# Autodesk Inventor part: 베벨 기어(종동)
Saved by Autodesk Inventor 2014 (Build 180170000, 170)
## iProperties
Created: 2026-05
Part Number: 베벨 기어(종동)
Material: 일반
Document SubType Name: Modeling
Designer: dg
Density: 1 g/cm^3
Appearance: 기본값
Author: dg
Author: jhkim
Creation Date: 2026-04-23
Sending System: Autodesk Inventor 2027
Preprocessor: ST-DEVELOPER v20.1
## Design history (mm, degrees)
node "베벨 기어(종동)1"
body "Solid1"
node "기준1"
